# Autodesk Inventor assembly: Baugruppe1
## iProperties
Created: 2004-12
Part Number: Baugruppe1
Document SubType Name: Assembly
Designer: marocsikf
Manufacturer: Standard
Standards Organization: Custom
Author: marocsikf
